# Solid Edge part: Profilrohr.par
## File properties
Username: bmolnar
Dokumentum tartalom típus: 0
Author: bmolnar
Last saved by: bmolnar
Revision: 91
Sűrűség: 0,000 kg/m^3
Pontosság: 0,990
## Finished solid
Body 1: solid body, 59 faces, 170 edges, 112 vertices.
  Faces by surface: plane 30, cylinder 29
  Edges by curve: line 112, circle 58
Bounding box of the edges (mm): 40.000 x 174.000 x 40.000, from (-20, -9.5, -20) to (20, 164.5, 20).
Cylindrical faces by radius (mm): R0.2 x12, R0.5 x12, R5 x4, R12.5 x1
Planar faces by outward normal: +x 7, +y 1, +z 7, -x 7, -y 1, -z 7
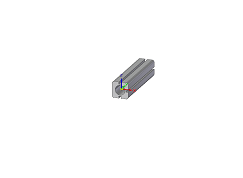
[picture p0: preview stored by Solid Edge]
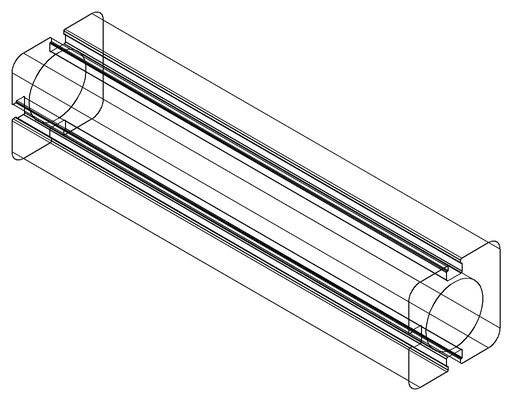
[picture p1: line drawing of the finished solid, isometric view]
